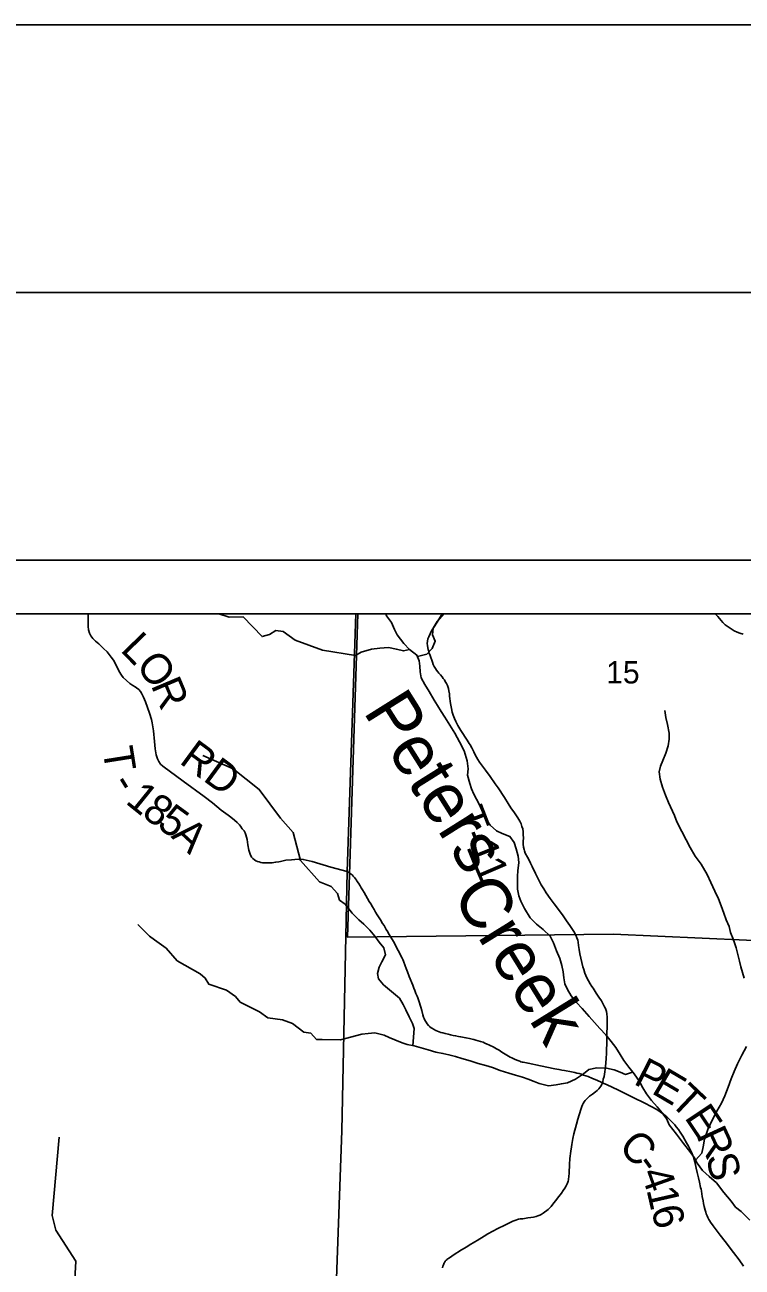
# Model space of a CAD drawing. Extents: x 0 to 34, y 0 to 22.
# Drawn here: x 28.135 to 29.474, y 19.68 to 22 of the extents above; entities that cross this region are included whole.
import ezdxf

# ---------------------------------------------------------------- set-up
doc = ezdxf.new("R2010")
doc.units = 0
for name, color, linetype in [('GM_X_Adjacent_County', 7, 'Continuous'), ('GM_X_County', 7, 'Continuous'), ('GM_X_County_Road', 7, 'Continuous'), ('GM_X_County_Road_Text', 7, 'Continuous'), ('GM_X_Minor_River', 7, 'Continuous'), ('GM_X_Minor_River_Text', 7, 'Continuous'), ('GM_X_Section', 7, 'Continuous'), ('GM_X_Section_Text', 7, 'Continuous'), ('GM_X_Township', 7, 'Continuous'), ('GM_X_Township_Road', 7, 'Continuous'), ('GM_X_Township_Road_Text', 7, 'Continuous'), ('SH_Border', 7, 'Continuous'), ('SH_Cut_Line', 7, 'Continuous'), ('SH_Data', 7, 'Continuous')]:
    doc.layers.add(name, color=color, linetype=linetype)

msp = doc.modelspace()

# ---------------------------------------------------------------- linework, layer by layer
at = {"layer": 'GM_X_Adjacent_County'}
for points in [[(28.7526, 20.9), (24.0167, 20.9), (24.0167, 14.1), (28.5181, 14.1)], [(28.5181, 14.1), (30.8167, 14.1), (30.8167, 20.9), (28.7526, 20.9)], [(28.7526, 20.9), (28.7366, 20.4185), (28.7263, 19.9342), (28.6656, 18.2443), (28.6433, 17.8576), (28.637, 17.506), (28.6368, 17.4981), (28.5999, 16.6109), (28.5991, 16.5887), (28.5955, 16.4142)], [(28.5955, 16.4142), (28.5991, 16.5887), (28.5999, 16.6109), (28.6368, 17.4981), (28.637, 17.506), (28.6433, 17.8576), (28.6656, 18.2443), (28.7263, 19.9342), (28.7366, 20.4185), (28.7526, 20.9)]]:
    msp.add_lwpolyline(points, dxfattribs=at)
at = {"layer": 'GM_X_County'}
for points in [[(28.7526, 20.9), (24.0167, 20.9), (24.0167, 14.1), (28.5181, 14.1)], [(28.5181, 14.1), (30.8167, 14.1), (30.8167, 20.9), (28.7526, 20.9)], [(28.5955, 16.4142), (28.5991, 16.5887), (28.5999, 16.6109), (28.6368, 17.4981), (28.637, 17.506), (28.6433, 17.8576), (28.6656, 18.2443), (28.7263, 19.9342), (28.7366, 20.4185), (28.7526, 20.9)], [(28.7526, 20.9), (28.7366, 20.4185), (28.7263, 19.9342), (28.6656, 18.2443), (28.6433, 17.8576), (28.637, 17.506), (28.6368, 17.4981), (28.5999, 16.6109), (28.5991, 16.5887), (28.5955, 16.4142)]]:
    msp.add_lwpolyline(points, dxfattribs=at)
at = {"layer": 'GM_X_County_Road'}
for points in [[(28.7366, 20.4185), (28.742, 20.4149), (28.744, 20.4135), (28.7457, 20.4121), (28.7478, 20.41), (28.7488, 20.4089), (28.7502, 20.4073), (28.7519, 20.4051), (28.7536, 20.4025), (28.7552, 20.4001), (28.7575, 20.3967), (28.7606, 20.3917), (28.7628, 20.3881), (28.7649, 20.3845), (28.7679, 20.3795), (28.7713, 20.3736), (28.7744, 20.3682), (28.7774, 20.3629), (28.7804, 20.3581), (28.7834, 20.3528), (28.7867, 20.3475), (28.7896, 20.3427), (28.7925, 20.338), (28.7961, 20.3322), (28.7987, 20.3281), (28.8026, 20.3217), (28.8052, 20.3175), (28.8092, 20.3105), (28.8121, 20.3058), (28.8138, 20.3031), (28.8181, 20.2958), (28.8229, 20.2876), (28.8317, 20.2712), (28.8389, 20.2569), (28.8402, 20.2541), (28.8415, 20.2512), (28.8448, 20.2427), (28.8467, 20.2374), (28.849, 20.2315), (28.8524, 20.2225), (28.8587, 20.2062), (28.8608, 20.2009), (28.8626, 20.1966), (28.8649, 20.1907), (28.8668, 20.186), (28.8682, 20.1824), (28.8701, 20.1773), (28.8737, 20.1655), (28.8755, 20.1593), (28.8779, 20.1512), (28.8792, 20.1467), (28.8803, 20.1438), (28.8815, 20.1411), (28.8825, 20.1392), (28.8836, 20.1372), (28.8857, 20.1341), (28.8882, 20.1312), (28.8901, 20.1294), (28.8935, 20.1267), (28.8956, 20.1253), (28.8978, 20.124), (28.9017, 20.1219), (28.9051, 20.1203), (28.908, 20.1192), (28.9113, 20.118), (28.9147, 20.1171), (28.9192, 20.1159), (28.9249, 20.1146), (28.9295, 20.1136), (28.9344, 20.1125), (28.9388, 20.1117), (28.9442, 20.1106), (28.9485, 20.1098), (28.9582, 20.108), (28.9648, 20.1066), (28.9697, 20.1056), (28.9728, 20.1048), (28.9768, 20.1039), (28.9811, 20.1026), (28.9854, 20.1012), (28.9901, 20.0996), (28.9935, 20.0982), (28.998, 20.0963), (29.0008, 20.0951), (29.0036, 20.0936), (29.0092, 20.0909), (29.0151, 20.0876), (29.0199, 20.0847), (29.0252, 20.0815), (29.0342, 20.0755), (29.0374, 20.0736), (29.0408, 20.0718), (29.044, 20.0703), (29.0485, 20.0682), (29.0534, 20.0661), (29.0567, 20.0648), (29.0587, 20.0641), (29.0608, 20.0634), (29.0628, 20.0628), (29.0648, 20.0624), (29.0742, 20.0604), (29.0972, 20.0558), (29.124, 20.0503), (29.1275, 20.0496), (29.1319, 20.0487), (29.1368, 20.0478), (29.1423, 20.0468), (29.1551, 20.0443), (29.1612, 20.0431), (29.1654, 20.0421), (29.1696, 20.0411), (29.1737, 20.0398), (29.1778, 20.0385), (29.186, 20.0355), (29.1945, 20.032), (29.2026, 20.0287), (29.212, 20.0245), (29.2127, 20.0241)], [(29.2127, 20.0241), (29.2202, 20.0208), (29.2429, 20.01), (29.2491, 20.007), (29.2592, 20.0022), (29.2718, 19.9959), (29.2906, 19.9866), (29.305, 19.9792), (29.3131, 19.9746), (29.3167, 19.9724), (29.3204, 19.97), (29.3266, 19.9654), (29.333, 19.9601), (29.3398, 19.9538), (29.3441, 19.9494), (29.3478, 19.9453), (29.3506, 19.942), (29.3547, 19.9366), (29.3578, 19.932), (29.3592, 19.93), (29.3627, 19.9242), (29.3699, 19.9119), (29.3733, 19.9059), (29.3768, 19.8994), (29.3792, 19.8945), (29.3806, 19.8913), (29.3818, 19.8882), (29.3827, 19.8855), (29.3837, 19.8825), (29.3843, 19.8806), (29.3852, 19.8765), (29.388, 19.8645), (29.3898, 19.8565), (29.392, 19.8462), (29.3939, 19.8383), (29.3962, 19.8284), (29.3969, 19.8251), (29.3977, 19.8214), (29.3993, 19.8114), (29.4009, 19.8033), (29.4018, 19.7983), (29.403, 19.7927), (29.4047, 19.7861), (29.4057, 19.7825), (29.4067, 19.7795), (29.4083, 19.7757), (29.4097, 19.7726), (29.4117, 19.7687), (29.4129, 19.7665), (29.4146, 19.7639), (29.4195, 19.7567), (29.4251, 19.7492), (29.4328, 19.7394), (29.4421, 19.7278), (29.4578, 19.707), (29.4679, 19.6931), (29.4762, 19.6813)]]:
    msp.add_lwpolyline(points, dxfattribs=at)
at = {"layer": 'GM_X_Minor_River'}
for points in [[(28.7518, 20.8222), (28.6902, 20.8323), (28.6393, 20.8507), (28.6172, 20.8668), (28.6035, 20.8689), (28.5915, 20.8612), (28.5776, 20.8573), (28.542, 20.8944), (28.5163, 20.8938), (28.4967, 20.9)], [(29.0545, 20.3855), (29.0543, 20.4097), (29.0549, 20.42), (29.0567, 20.4352), (29.0554, 20.4473), (29.0519, 20.4609), (29.048, 20.473), (29.0403, 20.4839), (29.0255, 20.4894), (29.0153, 20.4946), (29.0034, 20.5051), (28.9946, 20.5176), (28.983, 20.5447), (28.973, 20.5628), (28.9687, 20.573), (28.9653, 20.5828), (28.9609, 20.5987), (28.962, 20.6105), (28.9607, 20.6256), (28.9545, 20.6438), (28.9464, 20.6611), (28.9371, 20.6769), (28.9187, 20.7071), (28.9118, 20.7176), (28.9052, 20.7286), (28.8987, 20.7387), (28.8895, 20.7546), (28.8814, 20.7677), (28.8745, 20.7802), (28.8725, 20.7915), (28.872, 20.8022), (28.8708, 20.812), (28.8665, 20.8229), (28.8528, 20.833), (28.8421, 20.8447), (28.8298, 20.8609), (28.8248, 20.8707), (28.819, 20.8839), (28.8098, 20.8963), (28.8086, 20.9)], [(28.8674, 20.8205), (28.8854, 20.8246), (28.8952, 20.835), (28.9007, 20.8487), (28.8957, 20.8608), (28.8971, 20.8733), (28.9045, 20.8855), (28.917, 20.9)], [(28.8528, 20.833), (28.8415, 20.8307), (28.8282, 20.8336), (28.8138, 20.8368), (28.7971, 20.8355), (28.7816, 20.8342), (28.7624, 20.828), (28.7518, 20.8222)], [(29.4776, 20.2195), (29.4714, 20.2406), (29.469, 20.2509), (29.4663, 20.2614), (29.4627, 20.2762), (29.4573, 20.2913), (29.4522, 20.3049), (29.4495, 20.3158), (29.4441, 20.3283), (29.4394, 20.3408), (29.4348, 20.3544), (29.4293, 20.3676), (29.4224, 20.3819), (29.4154, 20.3981), (29.4081, 20.4132), (29.3973, 20.4325), (29.3862, 20.4475), (29.3766, 20.4633), (29.3689, 20.478), (29.3608, 20.4935), (29.3519, 20.5112), (29.3477, 20.5233), (29.3365, 20.5478), (29.3303, 20.5614), (29.3248, 20.5761), (29.3205, 20.5913), (29.3189, 20.6045), (29.3211, 20.6152), (29.3259, 20.6258), (29.3311, 20.6395), (29.3355, 20.6532), (29.3373, 20.6657), (29.3375, 20.6771), (29.3343, 20.693), (29.3312, 20.7062), (29.3296, 20.7191)], [(28.7329, 20.3576), (28.722, 20.3652), (28.7181, 20.3773), (28.7066, 20.3908), (28.6846, 20.3993), (28.6494, 20.4391), (28.6356, 20.4916), (28.6118, 20.5183), (28.5723, 20.5721), (28.5238, 20.6106), (28.4672, 20.6354)], [(29.4879, 19.7674), (29.4718, 19.7836), (29.4612, 19.7918), (29.4531, 19.8027), (29.4393, 19.8189), (29.4259, 19.8369), (29.4118, 19.8489), (29.3996, 19.8602), (29.3896, 19.8737), (29.3839, 19.8843), (29.3762, 19.8956), (29.3643, 19.9106), (29.3513, 19.9279), (29.3375, 19.9456), (29.3329, 19.9558), (29.3244, 19.9678), (29.3152, 19.9791), (29.3045, 19.9907), (29.2953, 20.0032), (29.2884, 20.0148), (29.2823, 20.0262), (29.2719, 20.0405), (29.262, 20.0529), (29.2531, 20.0657), (29.2462, 20.077), (29.2381, 20.0898), (29.2293, 20.1011), (29.219, 20.1138), (29.2083, 20.1255), (29.1884, 20.148), (29.175, 20.1627), (29.1643, 20.1739), (29.1544, 20.1864), (29.1475, 20.198), (29.1428, 20.2086), (29.1408, 20.2203), (29.1396, 20.2313), (29.1372, 20.243), (29.1333, 20.2559), (29.1271, 20.2706), (29.1217, 20.2853), (29.1155, 20.2978), (29.1021, 20.3102), (29.0899, 20.3203), (29.0781, 20.3323), (29.0677, 20.3496), (29.0604, 20.3632), (29.0569, 20.373), (29.0545, 20.3855)], [(28.8593, 20.0933), (28.8613, 20.1251), (28.8585, 20.1349), (28.8524, 20.147), (28.8462, 20.1602), (28.8408, 20.1704), (28.8339, 20.1821), (28.8045, 20.2072), (28.7949, 20.2181), (28.7933, 20.2283), (28.7962, 20.2401), (28.8014, 20.25), (28.8078, 20.2629), (28.8046, 20.2758), (28.7962, 20.2867), (28.7878, 20.298), (28.7786, 20.3093), (28.7675, 20.3201), (28.758, 20.3284), (28.7457, 20.3408), (28.7329, 20.3576)], [(28.724, 20.1043), (28.69, 20.1046), (28.6794, 20.105), (28.6683, 20.1166), (28.6558, 20.1184), (28.6341, 20.1345), (28.6155, 20.1418), (28.5886, 20.1453), (28.5726, 20.1565), (28.5368, 20.1743), (28.528, 20.1849), (28.5112, 20.1968), (28.4782, 20.2082), (28.4716, 20.2195), (28.4621, 20.2278), (28.4191, 20.2519), (28.3988, 20.2752), (28.3771, 20.2913), (28.3672, 20.298), (28.3454, 20.3198)], [(29.2693, 20.0438), (29.256, 20.0395), (29.2461, 20.044), (29.2347, 20.048), (29.2207, 20.0513), (29.2022, 20.0519), (29.1878, 20.0491), (29.1777, 20.041), (29.1626, 20.031), (29.1475, 20.0241), (29.1362, 20.0221), (29.1264, 20.0201), (29.1124, 20.018), (29.095, 20.0228), (29.0855, 20.0265), (29.0744, 20.0306), (29.0638, 20.0342), (29.0505, 20.0383), (29.038, 20.042), (29.0217, 20.0471), (29.0076, 20.0523), (28.9951, 20.0563), (28.9811, 20.0603), (28.9659, 20.0647), (28.9507, 20.0695), (28.9386, 20.0732), (28.9264, 20.0765), (28.915, 20.079), (28.9018, 20.0812), (28.8874, 20.0856), (28.8745, 20.0892), (28.8612, 20.0929), (28.8487, 20.0958), (28.8388, 20.0987), (28.8251, 20.1043), (28.8149, 20.1084), (28.8054, 20.1128), (28.7879, 20.1176), (28.7754, 20.1159), (28.7641, 20.1147), (28.724, 20.1043)], [(29.3865, 19.8794), (29.3982, 19.8927), (29.4007, 19.9041), (29.4036, 19.919), (29.4099, 19.9368), (29.4177, 19.9543), (29.4266, 19.9707), (29.4351, 19.986), (29.4415, 19.9997), (29.4477, 20.016), (29.4533, 20.0312), (29.4588, 20.0449), (29.4651, 20.0594), (29.4733, 20.0754), (29.4819, 20.0918)], [(28.2277, 19.6451), (28.2302, 19.691), (28.1926, 19.749), (28.1858, 19.7759), (28.199, 19.9227)]]:
    msp.add_lwpolyline(points, dxfattribs=at)
at = {"layer": 'GM_X_Section'}
msp.add_line((29.7552, 20.9), (28.7564, 20.9), dxfattribs=at)
msp.add_lwpolyline([(28.7564, 20.9), (28.7369, 20.296), (29.2336, 20.3016), (29.7299, 20.2792), (29.7552, 20.9)], dxfattribs=at)
at = {"layer": 'GM_X_Township'}
for points in [[(28.7526, 20.9), (24.0167, 20.9), (24.0167, 18.4402)], [(28.6656, 18.2443), (28.7263, 19.9342), (28.7366, 20.4185), (28.7526, 20.9)], [(28.7526, 20.9), (28.7366, 20.4185), (28.7263, 19.9342), (28.6656, 18.2443), (29.0347, 18.2309), (29.9568, 18.1999), (30.8167, 18.1651)], [(30.8167, 18.1651), (30.8167, 20.9), (28.7526, 20.9)]]:
    msp.add_lwpolyline(points, dxfattribs=at)
at = {"layer": 'GM_X_Township_Road'}
for points in [[(28.7366, 20.4185), (28.7058, 20.4269), (28.6708, 20.4374), (28.6546, 20.4412), (28.6449, 20.4415), (28.6325, 20.4407), (28.622, 20.4396), (28.612, 20.4375), (28.609, 20.4369), (28.6029, 20.4358), (28.5967, 20.435), (28.5905, 20.4346), (28.5843, 20.4346), (28.5781, 20.4351), (28.575, 20.4356), (28.572, 20.4364), (28.569, 20.4374), (28.5662, 20.4386), (28.5635, 20.4402), (28.5602, 20.4428), (28.558, 20.4455), (28.5554, 20.4512), (28.5529, 20.4582), (28.5513, 20.4682), (28.5497, 20.4784), (28.5475, 20.487), (28.5459, 20.4911), (28.544, 20.4943), (28.5407, 20.4985), (28.5371, 20.5036), (28.5352, 20.506), (28.531, 20.5104), (28.5264, 20.5146), (28.5191, 20.5202), (28.5143, 20.5241), (28.5014, 20.5334), (28.485, 20.5466), (28.4693, 20.5588), (28.4305, 20.5876), (28.3922, 20.6151), (28.3881, 20.6189), (28.3846, 20.624), (28.3822, 20.6292), (28.3801, 20.6367), (28.3779, 20.6478), (28.3765, 20.6613), (28.3747, 20.6813), (28.3725, 20.6966), (28.3712, 20.7024), (28.3674, 20.7141), (28.3636, 20.7252), (28.3598, 20.7354), (28.356, 20.7443), (28.3525, 20.7518), (28.3507, 20.7547), (28.3474, 20.7586), (28.3435, 20.7616), (28.3406, 20.7635), (28.3361, 20.7663), (28.3307, 20.7697), (28.3248, 20.7751), (28.3186, 20.781), (28.3151, 20.7856), (28.311, 20.7921), (28.3081, 20.7975), (28.3002, 20.8131), (28.2961, 20.8192), (28.2923, 20.824), (28.2883, 20.8287), (28.2818, 20.8354), (28.2728, 20.844), (28.2668, 20.8487), (28.2619, 20.8541), (28.2579, 20.8589), (28.2555, 20.8638), (28.2538, 20.8703), (28.2533, 20.8762), (28.253, 20.8829), (28.2533, 20.897), (28.2533, 20.9)], [(29.2127, 20.0241), (29.2134, 20.026), (29.2145, 20.0305), (29.216, 20.0359), (29.2176, 20.0445), (29.2188, 20.0543), (29.22, 20.0687), (29.2203, 20.0801), (29.2209, 20.1028), (29.2212, 20.1164), (29.2219, 20.1287), (29.222, 20.1364), (29.2218, 20.1424), (29.2216, 20.1464), (29.2211, 20.1526), (29.2203, 20.1569), (29.2198, 20.1591), (29.2185, 20.1627), (29.217, 20.1656), (29.2158, 20.1682), (29.2128, 20.1736), (29.2109, 20.1769), (29.2064, 20.184), (29.2015, 20.1912), (29.1974, 20.1975), (29.1954, 20.2005), (29.193, 20.2039), (29.1901, 20.2086), (29.1867, 20.2145), (29.1839, 20.2202), (29.1802, 20.229), (29.1781, 20.2354), (29.1765, 20.2405), (29.1723, 20.257), (29.1706, 20.265), (29.1696, 20.2731), (29.1685, 20.2806), (29.1675, 20.2867), (29.1667, 20.2906), (29.1654, 20.2945), (29.1631, 20.3), (29.1592, 20.3068), (29.1521, 20.3178), (29.1461, 20.3268), (29.1384, 20.3377), (29.1229, 20.3583), (29.1153, 20.3683), (29.108, 20.3786), (29.1032, 20.3864), (29.0985, 20.3938), (29.0942, 20.4022), (29.0882, 20.415), (29.0818, 20.4282), (29.0788, 20.4343), (29.0767, 20.4385), (29.0728, 20.4452), (29.0688, 20.4528), (29.0673, 20.4571), (29.0665, 20.4597), (29.0657, 20.464), (29.0652, 20.4698), (29.0652, 20.4754), (29.0653, 20.4809), (29.0652, 20.4875), (29.0648, 20.4925), (29.0642, 20.4982), (29.0627, 20.5029), (29.0609, 20.5075), (29.0586, 20.5126), (29.0552, 20.5188), (29.0488, 20.5284), (29.0419, 20.5378), (29.0368, 20.5456), (29.0299, 20.5566), (29.0182, 20.575), (29.0129, 20.5823), (29.0034, 20.5961), (28.9945, 20.6082), (28.9837, 20.6226), (28.9802, 20.6277), (28.9777, 20.632), (28.976, 20.6353), (28.9727, 20.642), (28.9689, 20.6498), (28.966, 20.6553), (28.9644, 20.6579), (28.9604, 20.6642), (28.9556, 20.6714), (28.9537, 20.6744), (28.9487, 20.6822), (28.943, 20.6915), (28.9393, 20.6986), (28.9367, 20.7046), (28.9343, 20.7105), (28.9325, 20.7165), (28.9309, 20.7231), (28.9294, 20.7323), (28.9277, 20.7459), (28.9273, 20.7502), (28.9264, 20.7563), (28.9254, 20.7607), (28.9237, 20.7658), (28.9219, 20.7695), (28.9207, 20.7717), (28.919, 20.7748), (28.918, 20.7764), (28.9158, 20.7793), (28.9135, 20.782), (28.9106, 20.7857), (28.9078, 20.789), (28.9057, 20.7915), (28.9034, 20.7948), (28.9014, 20.7975), (28.8991, 20.8013), (28.8972, 20.8054), (28.8955, 20.8099), (28.8912, 20.8218), (28.8895, 20.8266), (28.8887, 20.8291), (28.888, 20.8315), (28.8876, 20.8332), (28.8867, 20.8367), (28.8862, 20.8407), (28.886, 20.8444), (28.8864, 20.8487), (28.8873, 20.853), (28.8887, 20.8571), (28.8911, 20.8628), (28.8939, 20.868), (28.8986, 20.8755), (28.9044, 20.8844), (28.9121, 20.8966), (28.9142, 20.9)], [(29.4754, 20.8618), (29.4696, 20.8637), (29.4644, 20.8659), (29.4588, 20.8684), (29.4533, 20.8716), (29.4476, 20.8754), (29.442, 20.8795), (29.4394, 20.8818), (29.4374, 20.8839), (29.4342, 20.8874), (29.4281, 20.8947), (29.4234, 20.9)], [(28.9143, 19.6785), (28.9151, 19.6814), (28.916, 19.6837), (28.9167, 19.6858), (28.9175, 19.6875), (28.9185, 19.6892), (28.9196, 19.6907), (28.9209, 19.6924), (28.9222, 19.6935), (28.9233, 19.6945), (28.9244, 19.6952), (28.9261, 19.6964), (28.9291, 19.6984), (28.9342, 19.7019), (28.9501, 19.7117), (28.9596, 19.7176), (28.9643, 19.7205), (28.9749, 19.7271), (28.9791, 19.7297), (28.992, 19.7377), (28.999, 19.7418), (29.0174, 19.7518), (29.031, 19.7581), (29.0456, 19.7655), (29.0512, 19.7677), (29.0542, 19.7687), (29.0563, 19.7692), (29.0595, 19.7698), (29.0641, 19.7702), (29.0739, 19.7715), (29.0791, 19.7721), (29.0842, 19.773), (29.0891, 19.7741), (29.0926, 19.7752), (29.0963, 19.7769), (29.0988, 19.7782), (29.102, 19.7802), (29.1047, 19.7824), (29.1094, 19.7857), (29.1116, 19.7875), (29.1134, 19.7892), (29.1171, 19.7932), (29.1206, 19.7972), (29.1254, 19.8033), (29.1316, 19.8113), (29.1363, 19.8176), (29.1399, 19.8227), (29.1429, 19.8272), (29.1451, 19.8314), (29.1469, 19.835), (29.1481, 19.8383), (29.1488, 19.8404), (29.1493, 19.8426), (29.1496, 19.8446), (29.1501, 19.8481), (29.1507, 19.8556), (29.1514, 19.8712), (29.1523, 19.8828), (29.1538, 19.8963), (29.1549, 19.9042), (29.1556, 19.909), (29.1575, 19.9199), (29.1597, 19.9284), (29.1643, 19.9464), (29.1672, 19.9563), (29.1725, 19.9741), (29.1744, 19.9794), (29.1756, 19.9826), (29.1768, 19.9852), (29.1787, 19.9884), (29.1804, 19.9907), (29.1817, 19.9921), (29.1842, 19.9947), (29.189, 19.9987), (29.1945, 20.003), (29.1997, 20.007), (29.2031, 20.0097), (29.2061, 20.0125), (29.208, 20.0149), (29.2099, 20.0177), (29.2116, 20.0211), (29.2127, 20.0241)]]:
    msp.add_lwpolyline(points, dxfattribs=at)
at = {"layer": 'SH_Border'}
msp.add_lwpolyline([(2, 21.5), (33.5, 21.5), (33.5, 0.5), (2, 0.5)], close=True, dxfattribs=at)
at = {"layer": 'SH_Cut_Line'}
msp.add_lwpolyline([(0, 0), (34, 0), (34, 22), (0, 22)], close=True, dxfattribs=at)
at = {"layer": 'SH_Data'}
for points in [[(23.9167, 21), (30.9167, 21), (30.9167, 14), (23.9167, 14)], [(24.0167, 20.9), (30.8167, 20.9), (30.8167, 14.1), (24.0167, 14.1)]]:
    msp.add_lwpolyline(points, close=True, dxfattribs=at)

# ---------------------------------------------------------------- texts
at = {"layer": 'GM_X_County_Road_Text'}
for s, rotation, p in [('P', 333.078, (29.2689, 20.0225)), ('E', 329.4567, (29.3023, 20.0056)), ('T', 316.4638, (29.3362, 19.986)), ('E', 303.7364, (29.3648, 19.9593)), ('R', 294.8455, (29.3873, 19.926)), ('C', 314.8261, (29.2406, 19.9021)), ('S', 283.1535, (29.4059, 19.8865)), ('-', 305.9597, (29.272, 19.8708)), ('4', 289.4816, (29.2837, 19.8557)), ('1', 282.8093, (29.2949, 19.8244)), ('6', 284.8027, (29.3032, 19.7882))]:
    msp.add_text(s, height=0.0568, rotation=rotation, dxfattribs=at).set_placement(p)
at = {"layer": 'GM_X_Minor_River_Text'}
for s, rotation, p in [('Peters', 302.1382, (28.7652, 20.7174)), ('Creek', 301.6986, (28.9306, 20.3755))]:
    msp.add_text(s, height=0.09469, rotation=rotation, dxfattribs=at).set_placement(p)
at = {"layer": 'GM_X_Section_Text'}
msp.add_text('15', height=0.04186, rotation=0, dxfattribs=at).set_placement((29.22, 20.7698))
at = {"layer": 'GM_X_Township_Road_Text'}
for s, height, rotation, p in [('L', 0.0568, 314.0841, (28.3114, 20.8315)), ('O', 0.0568, 309.0103, (28.3401, 20.802)), ('R', 0.0568, 292.9495, (28.3694, 20.7667)), ('T', 0.0568, 279.0635, (28.2795, 20.6476)), ('RD', 0.05682, 323.718, (28.4212, 20.6222)), ('-', 0.0568, 301.5797, (28.2946, 20.5829)), ('1', 0.0568, 321.0564, (28.3207, 20.5473)), ('8', 0.0568, 324.2882, (28.3507, 20.5232)), ('5', 0.0568, 323.9566, (28.3791, 20.5028)), ('T', 0.0568, 291.164, (28.9343, 20.527)), ('A', 0.0568, 317.0483, (28.406, 20.4834)), ('-', 0.0568, 291.2821, (28.9497, 20.4873)), ('1', 0.0568, 291.7639, (28.9583, 20.465)), ('1', 0.0568, 293.2707, (28.9719, 20.431))]:
    msp.add_text(s, height=height, rotation=rotation, dxfattribs=at).set_placement(p)

doc.saveas('drawing.dxf')
